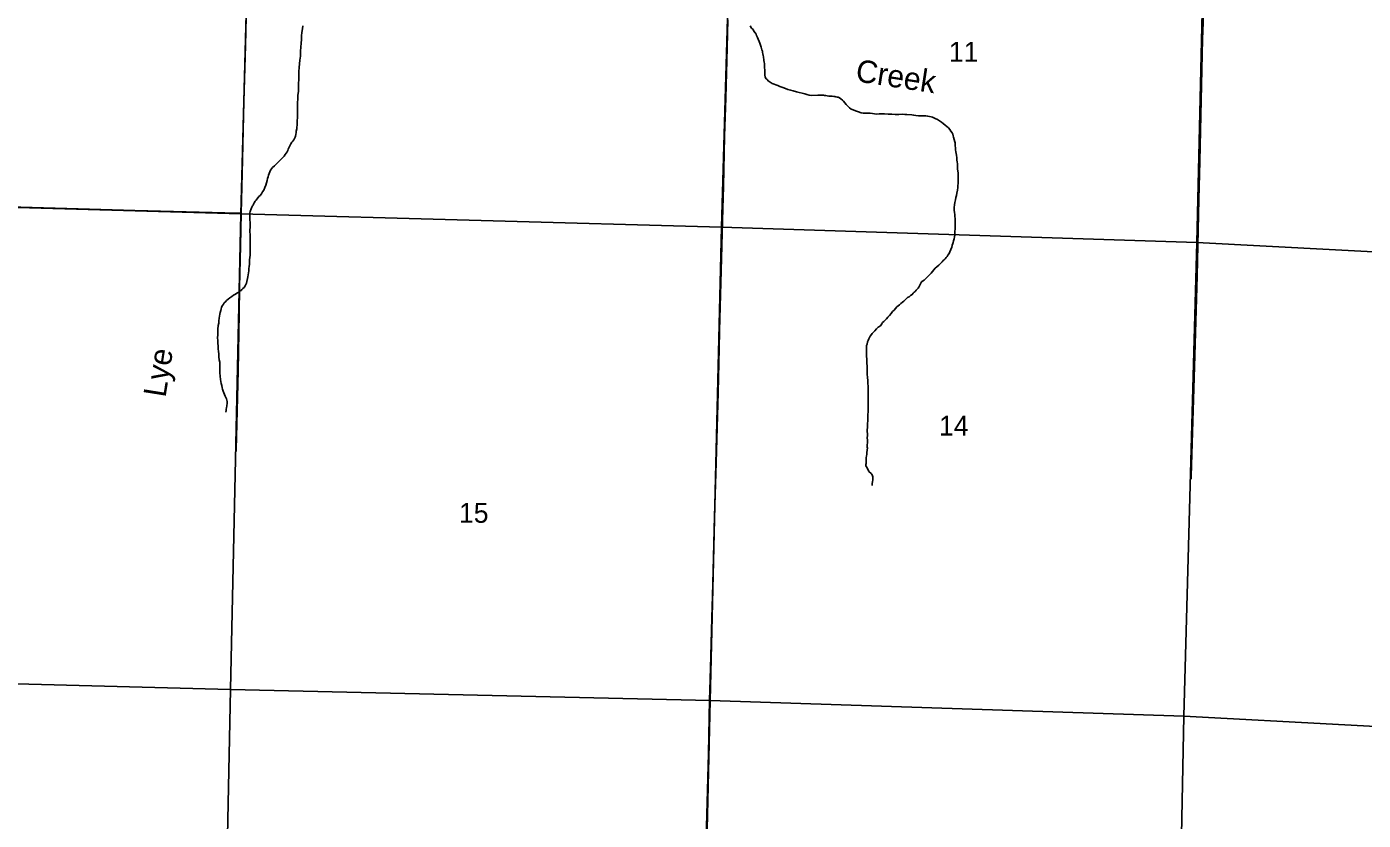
# Model space of a CAD drawing. Extents: x 1587405 to 1714697, y 1028970 to 1155083.
# Drawn here: x 1663879 to 1678758, y 1074942 to 1083782 of the extents above; entities that cross this region are included whole.
import ezdxf

# ---------------------------------------------------------------- set-up
doc = ezdxf.new("R2010")
doc.units = 0
for name, color, linetype in [('GM_X_County_Road', 7, 'Continuous'), ('GM_X_Minor_River', 7, 'Continuous'), ('GM_X_Minor_River_Text', 7, 'Continuous'), ('GM_X_Section', 7, 'Continuous'), ('GM_X_Section_Text', 7, 'Continuous'), ('GM_X_State_Route', 7, 'Continuous'), ('GM_X_Township_Road', 7, 'Continuous')]:
    doc.layers.add(name, color=color, linetype=linetype)

msp = doc.modelspace()

# ---------------------------------------------------------------- linework, layer by layer
at = {"layer": 'GM_X_County_Road'}
for points in [[(1666267, 1081705), (1666276, 1082145), (1666297, 1082948), (1666314, 1083572), (1666331, 1084211), (1666334, 1084353)], [(1666211, 1079051), (1666211, 1079077), (1666217, 1079356), (1666231, 1079947), (1666243, 1080586), (1666248, 1080882), (1666250, 1081029), (1666259, 1081341), (1666267, 1081705)]]:
    msp.add_lwpolyline(points, dxfattribs=at)
at = {"layer": 'GM_X_Minor_River'}
for points in [[(1666362, 1081684), (1666362, 1081695), (1666364, 1081707), (1666366, 1081723), (1666370, 1081733), (1666374, 1081743), (1666376, 1081753), (1666384, 1081771), (1666392, 1081785), (1666398, 1081795), (1666402, 1081807), (1666412, 1081819), (1666422, 1081837), (1666432, 1081851), (1666464, 1081889), (1666478, 1081903), (1666491, 1081921), (1666505, 1081941), (1666517, 1081961), (1666529, 1081991), (1666541, 1082015), (1666549, 1082043), (1666555, 1082067), (1666561, 1082091), (1666565, 1082111), (1666571, 1082129), (1666577, 1082147), (1666585, 1082167), (1666593, 1082185), (1666604, 1082199), (1666616, 1082213), (1666638, 1082233), (1666658, 1082255), (1666682, 1082277), (1666706, 1082301), (1666726, 1082323), (1666744, 1082341), (1666756, 1082357), (1666767, 1082373), (1666777, 1082389), (1666785, 1082403), (1666791, 1082418), (1666799, 1082440), (1666809, 1082456), (1666819, 1082476), (1666831, 1082494), (1666843, 1082508), (1666853, 1082522), (1666861, 1082536), (1666867, 1082550), (1666871, 1082564), (1666875, 1082582), (1666877, 1082602), (1666879, 1082620), (1666884, 1082644), (1666886, 1082664), (1666888, 1082686), (1666890, 1082710), (1666890, 1082736), (1666892, 1082766), (1666892, 1082794), (1666892, 1082825), (1666892, 1082857), (1666892, 1082893), (1666898, 1083019), (1666903, 1083059), (1666903, 1083103), (1666905, 1083150), (1666907, 1083194), (1666909, 1083238), (1666909, 1083284), (1666913, 1083328), (1666917, 1083368), (1666921, 1083410), (1666926, 1083454), (1666928, 1083511), (1666932, 1083555), (1666934, 1083597), (1666936, 1083639), (1666938, 1083679), (1666942, 1083719), (1666948, 1083757), (1666952, 1083791)], [(1671933, 1083792), (1671949, 1083767), (1671965, 1083749), (1671975, 1083731), (1671987, 1083713), (1671999, 1083697), (1672005, 1083683), (1672013, 1083663), (1672041, 1083597), (1672047, 1083576), (1672055, 1083554), (1672063, 1083526), (1672069, 1083508), (1672071, 1083494), (1672075, 1083478), (1672077, 1083460)], [(1672077, 1083460), (1672081, 1083448), (1672081, 1083436), (1672083, 1083422), (1672085, 1083406), (1672089, 1083388), (1672091, 1083372), (1672093, 1083358), (1672093, 1083338), (1672093, 1083321), (1672095, 1083305), (1672095, 1083283), (1672095, 1083265), (1672095, 1083253), (1672097, 1083241), (1672101, 1083223), (1672103, 1083213), (1672111, 1083203), (1672121, 1083193), (1672133, 1083179), (1672155, 1083163), (1672177, 1083151), (1672199, 1083143), (1672219, 1083136), (1672239, 1083128), (1672263, 1083116), (1672295, 1083106), (1672325, 1083094), (1672353, 1083084), (1672383, 1083076), (1672413, 1083066), (1672447, 1083057), (1672480, 1083049), (1672510, 1083041), (1672540, 1083033), (1672564, 1083025), (1672588, 1083019), (1672618, 1083017), (1672686, 1083019), (1672708, 1083018), (1672726, 1083018), (1672738, 1083018), (1672750, 1083018), (1672762, 1083016), (1672775, 1083014), (1672791, 1083012), (1672807, 1083010), (1672831, 1083008), (1672847, 1083008), (1672865, 1083006), (1672875, 1083004), (1672887, 1083002), (1672901, 1082998), (1672913, 1082996), (1672929, 1082990), (1672943, 1082980), (1672959, 1082965), (1672973, 1082951), (1672987, 1082935), (1673001, 1082917), (1673019, 1082897), (1673037, 1082879), (1673057, 1082865), (1673081, 1082855), (1673107, 1082843), (1673139, 1082832), (1673167, 1082824), (1673189, 1082820), (1673214, 1082818), (1673232, 1082818), (1673250, 1082818), (1673270, 1082818), (1673294, 1082814), (1673318, 1082810), (1673344, 1082808), (1673370, 1082810), (1673390, 1082812), (1673410, 1082812), (1673430, 1082811), (1673468, 1082809), (1673509, 1082807), (1673547, 1082805), (1673587, 1082805), (1673625, 1082807), (1673653, 1082805), (1673677, 1082803), (1673733, 1082800), (1673753, 1082796), (1673777, 1082792), (1673806, 1082790), (1673826, 1082790), (1673846, 1082790), (1673866, 1082790), (1673888, 1082788), (1673908, 1082786), (1673928, 1082782), (1673946, 1082778), (1673964, 1082774), (1673978, 1082768), (1673994, 1082761), (1674018, 1082747)], [(1674018, 1082747), (1674042, 1082733), (1674064, 1082719), (1674082, 1082703), (1674104, 1082685), (1674122, 1082671), (1674140, 1082655), (1674154, 1082637), (1674168, 1082618), (1674180, 1082600), (1674188, 1082586), (1674192, 1082568), (1674198, 1082550), (1674204, 1082524), (1674210, 1082500), (1674214, 1082488), (1674214, 1082474), (1674216, 1082456), (1674218, 1082432), (1674220, 1082410), (1674224, 1082389), (1674226, 1082371), (1674228, 1082351), (1674232, 1082323), (1674234, 1082297), (1674238, 1082275), (1674240, 1082255), (1674240, 1082233), (1674242, 1082211), (1674242, 1082195), (1674246, 1082175), (1674248, 1082149), (1674248, 1082129), (1674249, 1082108), (1674249, 1082080), (1674249, 1082056), (1674245, 1081992), (1674241, 1081960), (1674235, 1081926), (1674229, 1081900), (1674223, 1081878), (1674217, 1081852), (1674211, 1081824), (1674207, 1081798), (1674205, 1081768), (1674204, 1081739), (1674206, 1081711), (1674210, 1081691), (1674212, 1081669), (1674214, 1081645), (1674216, 1081623), (1674216, 1081601), (1674216, 1081575), (1674214, 1081549), (1674214, 1081527), (1674212, 1081503), (1674212, 1081479), (1674210, 1081458), (1674208, 1081442), (1674204, 1081420), (1674198, 1081396), (1674194, 1081378), (1674190, 1081366), (1674183, 1081348), (1674177, 1081324), (1674171, 1081310), (1674165, 1081300), (1674155, 1081274), (1674147, 1081254), (1674133, 1081238), (1674127, 1081224), (1674115, 1081210), (1674103, 1081198), (1674093, 1081186), (1674081, 1081176), (1674069, 1081162), (1674051, 1081146), (1674034, 1081126), (1674012, 1081108), (1673994, 1081092), (1673978, 1081074), (1673962, 1081056), (1673946, 1081038), (1673932, 1081022), (1673920, 1081010), (1673880, 1080970), (1673868, 1080960), (1673853, 1080948), (1673843, 1080942), (1673835, 1080932), (1673811, 1080882), (1673803, 1080870), (1673793, 1080858), (1673781, 1080846), (1673769, 1080834), (1673759, 1080824), (1673749, 1080814), (1673737, 1080798), (1673717, 1080786), (1673703, 1080774), (1673686, 1080764)], [(1666094, 1079488), (1666098, 1079508), (1666100, 1079522), (1666102, 1079538), (1666106, 1079560), (1666110, 1079590), (1666110, 1079606), (1666108, 1079623), (1666102, 1079637), (1666096, 1079651), (1666088, 1079667), (1666080, 1079685), (1666074, 1079705), (1666066, 1079723), (1666060, 1079743), (1666054, 1079761), (1666050, 1079787), (1666044, 1079807), (1666040, 1079829), (1666036, 1079852), (1666030, 1079928), (1666030, 1079954), (1666029, 1079986), (1666027, 1080016), (1666027, 1080044), (1666023, 1080070), (1666019, 1080106), (1666017, 1080137), (1666015, 1080165), (1666011, 1080195), (1666009, 1080225), (1666007, 1080255), (1666005, 1080285), (1666003, 1080315), (1666005, 1080349), (1666005, 1080381), (1666007, 1080413), (1666010, 1080454), (1666016, 1080480), (1666018, 1080506), (1666022, 1080534), (1666026, 1080558), (1666030, 1080580), (1666034, 1080600), (1666038, 1080620), (1666042, 1080638), (1666046, 1080654), (1666052, 1080666), (1666058, 1080678), (1666068, 1080692), (1666076, 1080706), (1666090, 1080718), (1666104, 1080732), (1666121, 1080746), (1666141, 1080760), (1666161, 1080776), (1666181, 1080790), (1666203, 1080802), (1666219, 1080812), (1666233, 1080822), (1666249, 1080836), (1666265, 1080844), (1666273, 1080854), (1666285, 1080866), (1666299, 1080878), (1666312, 1080896), (1666318, 1080910), (1666324, 1080926), (1666340, 1080994), (1666344, 1081018), (1666348, 1081040), (1666350, 1081064), (1666352, 1081087), (1666356, 1081111), (1666358, 1081135), (1666360, 1081161), (1666360, 1081185), (1666362, 1081211), (1666365, 1081237), (1666365, 1081267), (1666365, 1081293), (1666367, 1081317), (1666367, 1081339), (1666367, 1081361), (1666365, 1081381), (1666365, 1081404), (1666365, 1081428), (1666365, 1081450), (1666365, 1081472), (1666363, 1081494), (1666363, 1081518), (1666365, 1081544), (1666365, 1081562), (1666365, 1081580), (1666365, 1081594), (1666365, 1081608), (1666363, 1081624), (1666363, 1081640), (1666361, 1081654), (1666362, 1081670), (1666362, 1081684)], [(1673686, 1080764), (1673674, 1080754), (1673660, 1080740), (1673644, 1080724), (1673628, 1080712), (1673610, 1080698), (1673594, 1080684), (1673580, 1080672), (1673566, 1080660), (1673550, 1080642), (1673536, 1080626), (1673519, 1080608), (1673501, 1080586), (1673483, 1080566), (1673467, 1080548), (1673451, 1080528), (1673435, 1080512), (1673421, 1080498), (1673407, 1080486), (1673397, 1080472), (1673383, 1080450), (1673359, 1080434), (1673340, 1080416), (1673322, 1080396), (1673306, 1080380), (1673292, 1080366), (1673282, 1080352), (1673270, 1080336), (1673262, 1080320), (1673254, 1080306), (1673246, 1080288), (1673240, 1080272), (1673234, 1080246), (1673228, 1080230), (1673228, 1080214), (1673228, 1080196), (1673229, 1080179), (1673229, 1080163), (1673229, 1080149), (1673229, 1080129), (1673231, 1080061), (1673233, 1080029), (1673235, 1080003), (1673235, 1079973), (1673235, 1079943), (1673237, 1079911), (1673239, 1079874), (1673241, 1079840), (1673243, 1079806), (1673245, 1079776), (1673247, 1079746), (1673248, 1079720), (1673248, 1079700), (1673248, 1079666), (1673246, 1079634), (1673246, 1079608), (1673246, 1079575), (1673246, 1079531), (1673246, 1079491), (1673244, 1079461), (1673244, 1079441), (1673244, 1079417), (1673242, 1079389), (1673240, 1079367), (1673238, 1079343), (1673238, 1079319), (1673237, 1079293), (1673237, 1079270), (1673239, 1079252), (1673239, 1079230), (1673237, 1079202), (1673239, 1079178), (1673239, 1079152), (1673237, 1079120), (1673237, 1079098), (1673239, 1079086), (1673237, 1079070), (1673235, 1079060), (1673233, 1079044), (1673231, 1079032), (1673231, 1079020), (1673227, 1078998), (1673225, 1078982), (1673223, 1078968), (1673223, 1078949), (1673223, 1078929), (1673223, 1078915), (1673222, 1078905), (1673222, 1078891), (1673226, 1078881), (1673238, 1078859), (1673254, 1078829), (1673278, 1078805), (1673290, 1078789), (1673296, 1078779), (1673298, 1078767), (1673298, 1078751), (1673298, 1078735), (1673296, 1078712), (1673292, 1078694), (1673290, 1078672)]]:
    msp.add_lwpolyline(points, dxfattribs=at)
at = {"layer": 'GM_X_Section'}
for points in [[(1660988, 1087141), (1666402, 1086988), (1666262, 1081696), (1660899, 1081851)], [(1666402, 1086988), (1671767, 1086851), (1671613, 1081550), (1666262, 1081696)], [(1671767, 1086851), (1677028, 1086676), (1676906, 1081380), (1671613, 1081550)], [(1677028, 1086676), (1682413, 1086418), (1682308, 1081094), (1676906, 1081380)], [(1660899, 1081851), (1666262, 1081696), (1666146, 1076397), (1660810, 1076541)], [(1666262, 1081696), (1671613, 1081550), (1671489, 1076276), (1666146, 1076397)], [(1671613, 1081550), (1676906, 1081380), (1676759, 1076102), (1671489, 1076276)], [(1676906, 1081380), (1682308, 1081094), (1682137, 1075883), (1682136, 1075811), (1676759, 1076102)], [(1660810, 1076541), (1666146, 1076397), (1666038, 1071139), (1663189, 1071214), (1660729, 1071255)], [(1666146, 1076397), (1671489, 1076276), (1671364, 1071022), (1666038, 1071139)], [(1671489, 1076276), (1676759, 1076102), (1676658, 1070806), (1671364, 1071022)], [(1676759, 1076102), (1682136, 1075811), (1681969, 1070588), (1676658, 1070806)]]:
    msp.add_lwpolyline(points, close=True, dxfattribs=at)
at = {"layer": 'GM_X_State_Route'}
msp.add_lwpolyline([(1671684, 1083858), (1671676, 1083546), (1671660, 1082988), (1671648, 1082561), (1671634, 1082003), (1671628, 1081757), (1671610, 1081068), (1671592, 1080395), (1671587, 1080198), (1671575, 1079706), (1671553, 1078929), (1671550, 1078804), (1671537, 1078328), (1671519, 1077721), (1671514, 1077442), (1671505, 1077196), (1671494, 1076769), (1671483, 1076392), (1671480, 1076283), (1671467, 1075686), (1671444, 1074734)], dxfattribs=at)
at = {"layer": 'GM_X_Township_Road'}
for points in [[(1676982, 1084039), (1676982, 1084020), (1676970, 1083643), (1676938, 1082283), (1676927, 1081857), (1676908, 1081005), (1676882, 1080120), (1676843, 1078776), (1676842, 1078740)], [(1658214, 1081929), (1658814, 1081911), (1660061, 1081877), (1660668, 1081859), (1661554, 1081834), (1661915, 1081825), (1662128, 1081820), (1663047, 1081793), (1664064, 1081765), (1664326, 1081758), (1665081, 1081736), (1666229, 1081706), (1666267, 1081705)]]:
    msp.add_lwpolyline(points, dxfattribs=at)

# ---------------------------------------------------------------- texts
at = {"layer": 'GM_X_Minor_River_Text'}
for s, rotation, p in [('Creek', 351.3025, (1673097, 1083175)), ('Lye', 80.8773, (1665423, 1079645))]:
    msp.add_text(s, height=250, rotation=rotation, dxfattribs=at).set_placement(p)
at = {"layer": 'GM_X_Section_Text'}
for s, p in [('11', (1674145, 1083392)), ('14', (1674035, 1079227)), ('15', (1668691, 1078256))]:
    msp.add_text(s, height=221, rotation=0, dxfattribs=at).set_placement(p)

doc.saveas('drawing.dxf')
